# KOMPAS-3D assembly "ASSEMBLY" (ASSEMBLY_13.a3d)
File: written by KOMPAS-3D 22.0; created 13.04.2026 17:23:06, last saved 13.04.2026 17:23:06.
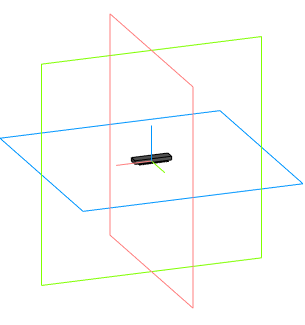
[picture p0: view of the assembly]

Document properties: Автор: Andrey; Полное имя файла: C:\Users\User1\Documents\ASSEMBLY_13.a3d

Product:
- Component [detail]: Body  | qty 1  | source file: Body_14.m3d
- Component [detail]: Pins  | qty 1  | source file: Pins_15.m3d
- Part/product: ASSEMBLY

Referenced files in C:\Users\User1\Documents\: Body_14.m3d, Pins_15.m3d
